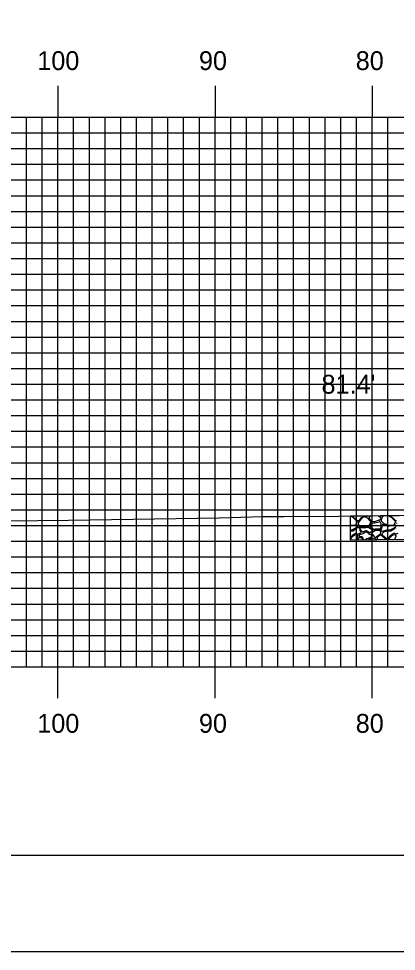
# Model space of a CAD drawing. Extents: x 1788943 to 1789287, y 442591 to 442811.
# Drawn here: x 1789006.7 to 1789030.7, y 442590.5 to 442649.9 of the extents above; entities that cross this region are included whole.
import ezdxf

# ---------------------------------------------------------------- set-up
doc = ezdxf.new("R2010")
doc.units = 0
for name, color, linetype in [('BORDER', 7, 'Continuous'), ('D_Roadway_SlopeLines', 7, 'Continuous'), ('D_Text_Standard', 7, 'Continuous'), ('H_V ANNOTATION', 7, 'Continuous'), ('MAJOR', 7, 'Continuous'), ('MINOR', 7, 'Continuous'), ('PLOT BOUNDARY', 7, 'Continuous'), ('S_Roadway_Centerline', 7, 'Continuous')]:
    doc.layers.add(name, color=color, linetype=linetype)

msp = doc.modelspace()

# ---------------------------------------------------------------- linework, layer by layer
at = {"layer": 'BORDER'}
msp.add_lwpolyline([(1788959.556, 442596.665), (1789279.556, 442596.665), (1789279.556, 442806.665), (1788959.556, 442806.665)], close=True, dxfattribs=at)
at = {"layer": 'D_Roadway_SlopeLines'}
for p, q in [((1789027.87, 442618.221), (1789027.8, 442618.259)), ((1789028.032, 442618.079), (1789027.88, 442618.213)), ((1789027.945, 442618.21), (1789028.096, 442618.079)), ((1789028.178, 442617.948), (1789028.032, 442618.079)), ((1789028.096, 442618.079), (1789028.205, 442617.984)), ((1789028.143, 442617.745), (1789028.194, 442617.886)), ((1789028.259, 442617.972), (1789028.313, 442617.989)), ((1789028.259, 442617.785), (1789028.317, 442617.633)), ((1789028.438, 442618.062), (1789028.267, 442617.84)), ((1789028.344, 442618.011), (1789028.389, 442618.079)), ((1789028.389, 442618.079), (1789028.431, 442618.14)), ((1789028.457, 442618.079), (1789028.448, 442618.071)), ((1789028.452, 442618.159), (1789028.529, 442618.197)), ((1789028.605, 442618.197), (1789028.457, 442618.079)), ((1789028.866, 442618.122), (1789028.662, 442618.206)), ((1789028.766, 442618.248), (1789028.71, 442618.269)), ((1789028.877, 442618.271), (1789028.805, 442618.247)), ((1789028.915, 442618.079), (1789028.885, 442618.11)), ((1789029.056, 442617.939), (1789028.915, 442618.079)), ((1789028.942, 442617.629), (1789029.066, 442617.873)), ((1789028.976, 442618.108), (1789028.969, 442618.184)), ((1789029.142, 442617.934), (1789028.994, 442618.072)), ((1789029.002, 442618.242), (1789029.074, 442618.273)), ((1789029.003, 442617.645), (1789029.113, 442617.834)), ((1789029.268, 442617.903), (1789029.171, 442617.92)), ((1789029.178, 442617.86), (1789029.268, 442617.835)), ((1789029.284, 442617.9), (1789029.268, 442617.903)), ((1789029.268, 442617.835), (1789029.296, 442617.827)), ((1789029.473, 442617.96), (1789029.313, 442617.903)), ((1789029.327, 442617.827), (1789029.606, 442617.907)), ((1789029.596, 442617.994), (1789029.477, 442617.961)), ((1789029.559, 442618.279), (1789029.632, 442618.219)), ((1789029.677, 442618.08), (1789029.625, 442618.014)), ((1789029.633, 442618.219), (1789029.683, 442618.179)), ((1789029.692, 442618.099), (1789029.677, 442618.08)), ((1789029.677, 442617.864), (1789029.73, 442617.627)), ((1789029.723, 442618.27), (1789029.742, 442618.281)), ((1789029.751, 442618.08), (1789029.723, 442618.017)), ((1789029.735, 442617.955), (1789029.875, 442617.808)), ((1789029.819, 442618.24), (1789029.751, 442618.08)), ((1789029.876, 442618.282), (1789029.847, 442618.269)), ((1789030.212, 442617.625), (1789029.866, 442617.729)), ((1789029.898, 442617.793), (1789030.225, 442617.68)), ((1789030.307, 442618.223), (1789030.192, 442618.286)), ((1789030.469, 442618.081), (1789030.318, 442618.215)), ((1789030.373, 442618.288), (1789030.372, 442618.287)), ((1789030.382, 442618.212), (1789030.533, 442618.081)), ((1789030.616, 442617.95), (1789030.469, 442618.081)), ((1789030.533, 442618.081), (1789030.642, 442617.986)), ((1789030.58, 442617.747), (1789030.631, 442617.888)), ((1789027.751, 442617.691), (1789027.788, 442617.678)), ((1789027.775, 442617.623), (1789027.751, 442617.63)), ((1789027.751, 442617.387), (1789027.883, 442617.398)), ((1789027.751, 442617.328), (1789027.904, 442617.324)), ((1789028.159, 442617.686), (1789027.801, 442617.622)), ((1789027.813, 442617.675), (1789028.096, 442617.708)), ((1789028.103, 442617.147), (1789027.865, 442617.002)), ((1789027.905, 442617.404), (1789028.201, 442617.56)), ((1789027.939, 442617.335), (1789028.158, 442617.5)), ((1789028.195, 442617.103), (1789028.134, 442617.146)), ((1789028.175, 442617.509), (1789028.255, 442617.534)), ((1789028.356, 442617.152), (1789028.221, 442617.099)), ((1789028.229, 442617.626), (1789028.224, 442617.645)), ((1789028.326, 442617.499), (1789028.341, 442617.457)), ((1789028.343, 442617.449), (1789028.359, 442617.372)), ((1789028.364, 442617.597), (1789028.601, 442617.57)), ((1789028.436, 442617.222), (1789028.365, 442617.157)), ((1789028.365, 442617.086), (1789028.588, 442617.164)), ((1789028.383, 442617.433), (1789028.375, 442617.479)), ((1789028.388, 442617.333), (1789028.424, 442617.315)), ((1789028.511, 442617.273), (1789028.396, 442617.407)), ((1789028.44, 442617.545), (1789028.649, 442617.514)), ((1789028.751, 442617.327), (1789028.575, 442617.257)), ((1789028.6, 442617.17), (1789028.733, 442617.256)), ((1789028.613, 442617.57), (1789028.897, 442617.598)), ((1789028.665, 442617.514), (1789028.906, 442617.548)), ((1789028.791, 442617.258), (1789028.902, 442617.2)), ((1789028.982, 442617.218), (1789028.801, 442617.323)), ((1789028.932, 442617.156), (1789028.932, 442617.152)), ((1789028.946, 442617.538), (1789029.148, 442617.399)), ((1789029.231, 442617.407), (1789029.018, 442617.571)), ((1789029.152, 442617.308), (1789029.047, 442617.223)), ((1789029.269, 442616.999), (1789029.147, 442617.146)), ((1789029.157, 442617.229), (1789029.268, 442617.31)), ((1789029.268, 442617.31), (1789029.336, 442617.36)), ((1789029.354, 442617.423), (1789029.285, 442617.398)), ((1789029.37, 442617.371), (1789029.602, 442617.372)), ((1789029.623, 442617.437), (1789029.371, 442617.426)), ((1789029.674, 442617.122), (1789029.411, 442616.914)), ((1789029.658, 442617.328), (1789029.693, 442617.181)), ((1789029.726, 442617.591), (1789029.673, 442617.471)), ((1789029.748, 442617.458), (1789029.715, 442617.379)), ((1789029.794, 442617.685), (1789029.751, 442617.469)), ((1789029.781, 442617.302), (1789030.101, 442617.381)), ((1789029.79, 442617.159), (1789029.872, 442617.245)), ((1789029.896, 442617.26), (1789030.122, 442617.329)), ((1789030.11, 442617.382), (1789030.321, 442617.4)), ((1789030.14, 442617.331), (1789030.341, 442617.326)), ((1789030.596, 442617.688), (1789030.238, 442617.624)), ((1789030.25, 442617.678), (1789030.533, 442617.71)), ((1789030.54, 442617.149), (1789030.303, 442617.004)), ((1789030.343, 442617.407), (1789030.638, 442617.563)), ((1789030.377, 442617.338), (1789030.595, 442617.502)), ((1789030.632, 442617.105), (1789030.571, 442617.148)), ((1789030.612, 442617.511), (1789030.692, 442617.536)), ((1789030.794, 442617.154), (1789030.659, 442617.102)), ((1789030.666, 442617.628), (1789030.661, 442617.647)), ((1789027.858, 442616.995), (1789027.751, 442616.855)), ((1789027.843, 442616.895), (1789027.752, 442616.759)), ((1789028.031, 442617.048), (1789027.849, 442616.901)), ((1789028.175, 442617.078), (1789028.044, 442617.054)), ((1789028.156, 442616.763), (1789028.24, 442616.983)), ((1789028.238, 442617.008), (1789028.205, 442617.064)), ((1789028.249, 442616.764), (1789028.294, 442616.877)), ((1789028.322, 442616.895), (1789028.476, 442616.89)), ((1789028.331, 442617.01), (1789028.329, 442617.019)), ((1789028.517, 442616.938), (1789028.375, 442616.967)), ((1789028.501, 442616.873), (1789028.547, 442616.768)), ((1789028.579, 442616.813), (1789028.562, 442616.894)), ((1789028.631, 442616.769), (1789028.629, 442616.769)), ((1789028.764, 442616.803), (1789028.733, 442616.776)), ((1789028.87, 442616.826), (1789028.794, 442616.816)), ((1789029.046, 442616.897), (1789028.885, 442616.83)), ((1789028.974, 442616.797), (1789029.116, 442616.873)), ((1789028.983, 442617.102), (1789029.068, 442617.093)), ((1789029.114, 442617.014), (1789029.076, 442616.927)), ((1789029.158, 442616.878), (1789029.269, 442616.849)), ((1789029.331, 442616.922), (1789029.269, 442616.999)), ((1789029.269, 442616.849), (1789029.358, 442616.825)), ((1789029.387, 442616.807), (1789029.412, 442616.778)), ((1789029.473, 442616.822), (1789029.501, 442616.779)), ((1789029.654, 442617.047), (1789029.483, 442616.896)), ((1789030.004, 442616.799), (1789029.73, 442617.046)), ((1789029.886, 442616.977), (1789029.79, 442617.081)), ((1789030.112, 442616.804), (1789029.89, 442616.974)), ((1789030.295, 442616.997), (1789030.152, 442616.81)), ((1789030.28, 442616.897), (1789030.207, 442616.787)), ((1789030.469, 442617.05), (1789030.286, 442616.903)), ((1789030.612, 442617.08), (1789030.481, 442617.056)), ((1789030.603, 442616.792), (1789030.677, 442616.985)), ((1789030.675, 442617.01), (1789030.642, 442617.066))]:
    msp.add_line(p, q, dxfattribs=at)
msp.add_lwpolyline([(1789041.251, 442618.41), (1789027.751, 442618.259), (1789027.751, 442616.759), (1789043.237, 442616.938)], dxfattribs=at)
for centre, radius, start, end in [((1789027.842, 442618.171), 0.057, 48.29123, 61.34407), ((1789027.982, 442618.253), 0.057, 172.23626, 228.94372), ((1789028.09, 442617.765), 0.057, 276.57451, 340.12954), ((1789028.14, 442617.905), 0.057, 340.12954, 48.29123), ((1789028.242, 442618.027), 0.057, 228.94372, 286.90842), ((1789028.312, 442617.805), 0.057, 142.27433, 200.97452), ((1789028.296, 442618.043), 0.057, 286.90842, 325.83432), ((1789028.478, 442618.108), 0.057, 116.61507, 145.83432), ((1789028.483, 442618.027), 0.057, 128.70983, 142.27433), ((1789028.504, 442618.248), 0.057, 296.61507, 20.01621), ((1789028.641, 442618.153), 0.057, 67.74381, 128.70983), ((1789028.787, 442618.301), 0.057, 249.07652, 288.48497), ((1789028.845, 442618.069), 0.057, 45.05002, 67.74381), ((1789029.025, 442618.189), 0.057, 114.01251, 185.24445), ((1789029.032, 442618.113), 0.057, 185.24445, 216.63173), ((1789029.032, 442618.113), 0.057, 216.63173, 227.17111), ((1789029.015, 442617.899), 0.057, 333.01916, 45.05002), ((1789029.162, 442617.805), 0.057, 74.10462, 149.8765), ((1789029.18, 442617.976), 0.057, 227.17111, 260.18421), ((1789029.294, 442617.956), 0.057, 260.18421, 289.70384), ((1789029.312, 442617.881), 0.057, 254.10462, 285.99541), ((1789029.492, 442617.906), 0.057, 105.30514, 109.70384), ((1789029.581, 442618.049), 0.057, 285.30514, 322.00297), ((1789029.622, 442617.852), 0.057, 12.45744, 105.99541), ((1789029.668, 442618.264), 0.057, 230.95616, 231.39021), ((1789029.695, 442618.32), 0.057, 225.24975, 298.80751), ((1789029.647, 442618.134), 0.057, 322.00298, 51.39021), ((1789029.776, 442617.994), 0.057, 156.69445, 223.62324), ((1789029.85, 442617.674), 0.057, 73.317, 168.75668), ((1789029.872, 442618.217), 0.057, 115.45393, 156.69445), ((1789029.916, 442617.847), 0.057, 223.62324, 250.98617), ((1789030.28, 442618.173), 0.057, 48.29123, 61.34406), ((1789030.42, 442618.255), 0.057, 146.05356, 228.94373), ((1789030.527, 442617.767), 0.057, 276.57451, 340.12954), ((1789030.578, 442617.907), 0.057, 340.12954, 48.29123), ((1789030.679, 442618.029), 0.057, 228.94373, 286.90842), ((1789030.749, 442617.808), 0.057, 142.27433, 200.97452), ((1789027.791, 442617.678), 0.057, 253.317, 280.20428), ((1789027.806, 442617.732), 0.057, 250.98617, 276.57451), ((1789027.879, 442617.455), 0.057, 274.81366, 297.85148), ((1789027.905, 442617.381), 0.057, 268.48066, 307.03879), ((1789028.118, 442617.123), 0.0285, 54.51234, 121.42302), ((1789028.192, 442617.455), 0.057, 107.33152, 127.03879), ((1789028.169, 442617.63), 0.057, 15.57413, 100.20428), ((1789028.174, 442617.611), 0.057, 297.85148, 15.57413), ((1789028.272, 442617.48), 0.057, 19.58667, 107.33152), ((1789028.37, 442617.654), 0.057, 200.97452, 263.56694), ((1789028.287, 442617.438), 0.057, 11.68365, 19.58667), ((1789028.346, 442617.178), 0.0285, 291.24407, 312.25732), ((1789028.415, 442617.384), 0.057, 191.68365, 242.40404), ((1789028.431, 442617.489), 0.057, 81.57887, 190.35486), ((1789028.44, 442617.444), 0.057, 190.35486, 220.65131), ((1789028.398, 442617.264), 0.057, 312.25732, 62.40404), ((1789028.554, 442617.31), 0.057, 220.65131, 291.59099), ((1789028.569, 442617.218), 0.057, 289.45599, 302.73057), ((1789028.607, 442617.627), 0.057, 263.56694, 275.64936), ((1789028.657, 442617.571), 0.057, 261.57887, 277.99349), ((1789028.764, 442617.208), 0.057, 62.20244, 122.73057), ((1789028.772, 442617.274), 0.057, 59.98143, 111.59099), ((1789028.891, 442617.655), 0.057, 275.64936, 333.01916), ((1789028.875, 442617.149), 0.057, 6.89279, 62.20244), ((1789028.914, 442617.492), 0.057, 55.48749, 97.99349), ((1789028.989, 442617.159), 0.057, 186.89279, 263.99583), ((1789029.011, 442617.267), 0.057, 239.98144, 308.93451), ((1789029.052, 442617.616), 0.057, 149.8765, 232.35578), ((1789029.191, 442617.183), 0.057, 126.26926, 219.52121), ((1789029.116, 442617.352), 0.057, 308.93451, 55.48749), ((1789029.266, 442617.452), 0.057, 232.35578, 272.72879), ((1789029.266, 442617.452), 0.057, 272.72879, 289.49005), ((1789029.37, 442617.314), 0.057, 90.13879, 126.26926), ((1789029.373, 442617.369), 0.057, 92.48667, 109.49005), ((1789029.602, 442617.315), 0.057, 13.63196, 90.13879), ((1789029.621, 442617.494), 0.057, 272.48667, 336.08753), ((1789029.638, 442617.167), 0.057, 308.42302, 13.63196), ((1789029.768, 442617.357), 0.057, 157.52754, 283.9095), ((1789029.674, 442617.614), 0.057, 336.08753, 12.45744), ((1789029.695, 442617.48), 0.057, 337.52755, 348.75668), ((1789029.831, 442617.12), 0.057, 136.41395, 222.83909), ((1789029.913, 442617.206), 0.057, 106.94867, 136.41395), ((1789030.115, 442617.326), 0.057, 94.81366, 103.9095), ((1789030.139, 442617.274), 0.057, 88.48066, 106.94867), ((1789030.228, 442617.68), 0.057, 253.317, 280.20428), ((1789030.243, 442617.734), 0.057, 250.98617, 276.57451), ((1789030.316, 442617.457), 0.057, 274.81366, 297.85148), ((1789030.342, 442617.383), 0.057, 268.48066, 307.03879), ((1789030.555, 442617.125), 0.0285, 54.51234, 121.42302), ((1789030.629, 442617.457), 0.057, 107.33152, 127.03879), ((1789030.606, 442617.632), 0.057, 15.57413, 100.20428), ((1789030.611, 442617.613), 0.057, 297.85148, 15.57413), ((1789027.866, 442616.879), 0.0285, 128.82419, 146.35995), ((1789027.88, 442616.978), 0.0285, 121.42302, 142.64466), ((1789028.049, 442617.026), 0.0285, 100.25399, 128.82419), ((1789028.18, 442617.05), 0.0285, 30.70069, 100.25399), ((1789028.211, 442617.126), 0.0285, 234.51234, 291.24407), ((1789028.213, 442616.994), 0.0285, 339.05716, 30.70069), ((1789028.321, 442616.866), 0.0285, 88.17214, 158.24861), ((1789028.384, 442617.032), 0.057, 109.45599, 193.18404), ((1789028.387, 442617.023), 0.057, 193.18404, 258.41638), ((1789028.475, 442616.861), 0.0285, 23.79951, 88.17214), ((1789028.506, 442616.882), 0.057, 12.45744, 78.41638), ((1789028.635, 442616.826), 0.057, 192.45744, 264.33942), ((1789028.696, 442616.82), 0.057, 299.16504, 310.41455), ((1789028.801, 442616.76), 0.057, 97.17503, 130.41455), ((1789028.863, 442616.882), 0.057, 277.17503, 292.66988), ((1789029.001, 442616.747), 0.057, 118.1225, 153.45085), ((1789029.024, 442616.949), 0.057, 292.66988, 336.36793), ((1789029.062, 442617.037), 0.057, 336.36793, 83.99583), ((1789029.143, 442616.823), 0.057, 75.30645, 118.1225), ((1789029.375, 442616.959), 0.057, 219.52121, 308.42302), ((1789029.344, 442616.77), 0.057, 40.00757, 75.30646), ((1789029.52, 442616.853), 0.057, 131.29626, 213.01256), ((1789029.692, 442617.004), 0.057, 47.9276, 131.29626), ((1789029.907, 442616.996), 0.0285, 222.83909, 232.64466), ((1789029.966, 442616.756), 0.057, 29.78803, 47.9276), ((1789030.129, 442616.827), 0.0285, 232.64466, 322.64466), ((1789030.304, 442616.881), 0.0285, 128.82419, 146.35995), ((1789030.317, 442616.98), 0.0285, 121.42302, 142.64466), ((1789030.486, 442617.028), 0.0285, 100.25399, 128.82419), ((1789030.617, 442617.052), 0.0285, 30.70069, 100.25399), ((1789030.648, 442617.128), 0.0285, 234.51234, 291.24408), ((1789030.651, 442616.996), 0.0285, 339.05716, 30.70068)]:
    msp.add_arc(centre, radius, start, end, dxfattribs=at)
at = {"layer": 'MAJOR'}
for p, q in [((1789009.156, 442645.669), (1789009.156, 442643.665)), ((1789019.156, 442645.669), (1789019.156, 442643.665)), ((1789029.156, 442645.669), (1789029.156, 442643.665)), ((1788969.156, 442643.665), (1789249.156, 442643.665)), ((1788969.156, 442643.665), (1789249.156, 442643.665)), ((1789009.156, 442608.665), (1789009.156, 442643.665)), ((1789019.156, 442608.665), (1789019.156, 442643.665)), ((1789029.156, 442608.665), (1789029.156, 442643.665)), ((1788969.156, 442638.665), (1789249.156, 442638.665)), ((1788969.156, 442633.665), (1789249.156, 442633.665)), ((1788969.156, 442628.665), (1789249.156, 442628.665)), ((1788969.156, 442623.665), (1789249.156, 442623.665)), ((1788969.156, 442618.665), (1789249.156, 442618.665)), ((1788969.156, 442613.665), (1789249.156, 442613.665)), ((1788969.156, 442608.665), (1789249.156, 442608.665)), ((1788969.156, 442608.665), (1789249.156, 442608.665)), ((1789009.156, 442606.661), (1789009.156, 442608.665)), ((1789019.156, 442606.661), (1789019.156, 442608.665)), ((1789029.156, 442606.661), (1789029.156, 442608.665))]:
    msp.add_line(p, q, dxfattribs=at)
at = {"layer": 'MINOR'}
for p, q in [((1789007.156, 442608.665), (1789007.156, 442643.665)), ((1789008.156, 442608.665), (1789008.156, 442643.665)), ((1789010.156, 442608.665), (1789010.156, 442643.665)), ((1789011.156, 442608.665), (1789011.156, 442643.665)), ((1789012.156, 442608.665), (1789012.156, 442643.665)), ((1789013.156, 442608.665), (1789013.156, 442643.665)), ((1789014.156, 442608.665), (1789014.156, 442643.665)), ((1789015.156, 442608.665), (1789015.156, 442643.665)), ((1789016.156, 442608.665), (1789016.156, 442643.665)), ((1789017.156, 442608.665), (1789017.156, 442643.665)), ((1789018.156, 442608.665), (1789018.156, 442643.665)), ((1789020.156, 442608.665), (1789020.156, 442643.665)), ((1789021.156, 442608.665), (1789021.156, 442643.665)), ((1789022.156, 442608.665), (1789022.156, 442643.665)), ((1789023.156, 442608.665), (1789023.156, 442643.665)), ((1789024.156, 442608.665), (1789024.156, 442643.665)), ((1789025.156, 442608.665), (1789025.156, 442643.665)), ((1789026.156, 442608.665), (1789026.156, 442643.665)), ((1789027.156, 442608.665), (1789027.156, 442643.665)), ((1789028.156, 442608.665), (1789028.156, 442643.665)), ((1789030.156, 442608.665), (1789030.156, 442643.665)), ((1788969.156, 442642.665), (1789249.156, 442642.665)), ((1788969.156, 442641.665), (1789249.156, 442641.665)), ((1788969.156, 442640.665), (1789249.156, 442640.665)), ((1788969.156, 442639.665), (1789249.156, 442639.665)), ((1788969.156, 442637.665), (1789249.156, 442637.665)), ((1788969.156, 442636.665), (1789249.156, 442636.665)), ((1788969.156, 442635.665), (1789249.156, 442635.665)), ((1788969.156, 442634.665), (1789249.156, 442634.665)), ((1788969.156, 442632.665), (1789249.156, 442632.665)), ((1788969.156, 442631.665), (1789249.156, 442631.665)), ((1788969.156, 442630.665), (1789249.156, 442630.665)), ((1788969.156, 442629.665), (1789249.156, 442629.665)), ((1788969.156, 442627.665), (1789249.156, 442627.665)), ((1788969.156, 442626.665), (1789249.156, 442626.665)), ((1788969.156, 442625.665), (1789249.156, 442625.665)), ((1788969.156, 442624.665), (1789249.156, 442624.665)), ((1788969.156, 442622.665), (1789249.156, 442622.665)), ((1788969.156, 442621.665), (1789249.156, 442621.665)), ((1788969.156, 442620.665), (1789249.156, 442620.665)), ((1788969.156, 442619.665), (1789249.156, 442619.665)), ((1788969.156, 442617.665), (1789249.156, 442617.665)), ((1788969.156, 442616.665), (1789249.156, 442616.665)), ((1788969.156, 442615.665), (1789249.156, 442615.665)), ((1788969.156, 442614.665), (1789249.156, 442614.665)), ((1788969.156, 442612.665), (1789249.156, 442612.665)), ((1788969.156, 442611.665), (1789249.156, 442611.665)), ((1788969.156, 442610.665), (1789249.156, 442610.665)), ((1788969.156, 442609.665), (1789249.156, 442609.665))]:
    msp.add_line(p, q, dxfattribs=at)
at = {"layer": 'PLOT BOUNDARY'}
msp.add_lwpolyline([(1788943.37, 442590.547), (1789283.37, 442590.547), (1789283.37, 442810.547), (1788943.37, 442810.547)], close=True, dxfattribs=at)
at = {"layer": 'S_Roadway_Centerline'}
msp.add_lwpolyline([(1788969.156, 442617.569), (1788973.285, 442617.634), (1788982.181, 442617.707), (1788987.038, 442617.772), (1788992.322, 442617.811), (1789009.825, 442618), (1789019.422, 442618.161), (1789022.182, 442618.24), (1789023.54, 442618.238), (1789027.03, 442618.251), (1789042.369, 442618.422), (1789055.183, 442618.673), (1789079.24, 442619.18)], dxfattribs=at)

# ---------------------------------------------------------------- texts
at = {"layer": 'D_Text_Standard'}
msp.add_text("81.4'", height=1.2, dxfattribs=at).set_placement((1789025.93, 442626.06))
at = {"layer": 'H_V ANNOTATION'}
for s, p in [('100', (1789007.84, 442646.665)), ('90', (1789018.129, 442646.665)), ('80', (1789028.107, 442646.665)), ('100', (1789007.84, 442604.465)), ('90', (1789018.129, 442604.465)), ('80', (1789028.107, 442604.465))]:
    msp.add_text(s, height=1.2, dxfattribs=at).set_placement(p)

doc.saveas('drawing.dxf')
